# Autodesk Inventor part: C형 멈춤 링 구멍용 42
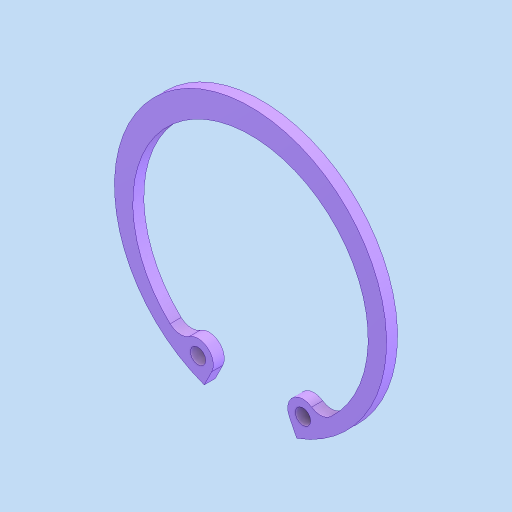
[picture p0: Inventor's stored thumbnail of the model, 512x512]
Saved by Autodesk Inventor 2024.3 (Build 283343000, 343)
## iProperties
Created: 2025-11
Part Number: C형 멈춤 링 구멍용 42
Material: 강철, 연강
Description: 리테이닝 링(C형)
Document SubType Name: Modeling
Designer: PC2-02
Density: 7.85 g/cm^3
Appearance: 기본값
Author: jhkim
Sending System: Autodesk Inventor 2026
Preprocessor: ST-DEVELOPER v20.1
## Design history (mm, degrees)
node "C형 멈춤링 구멍용 421"
node "솔리드1"
body "Solid1"
